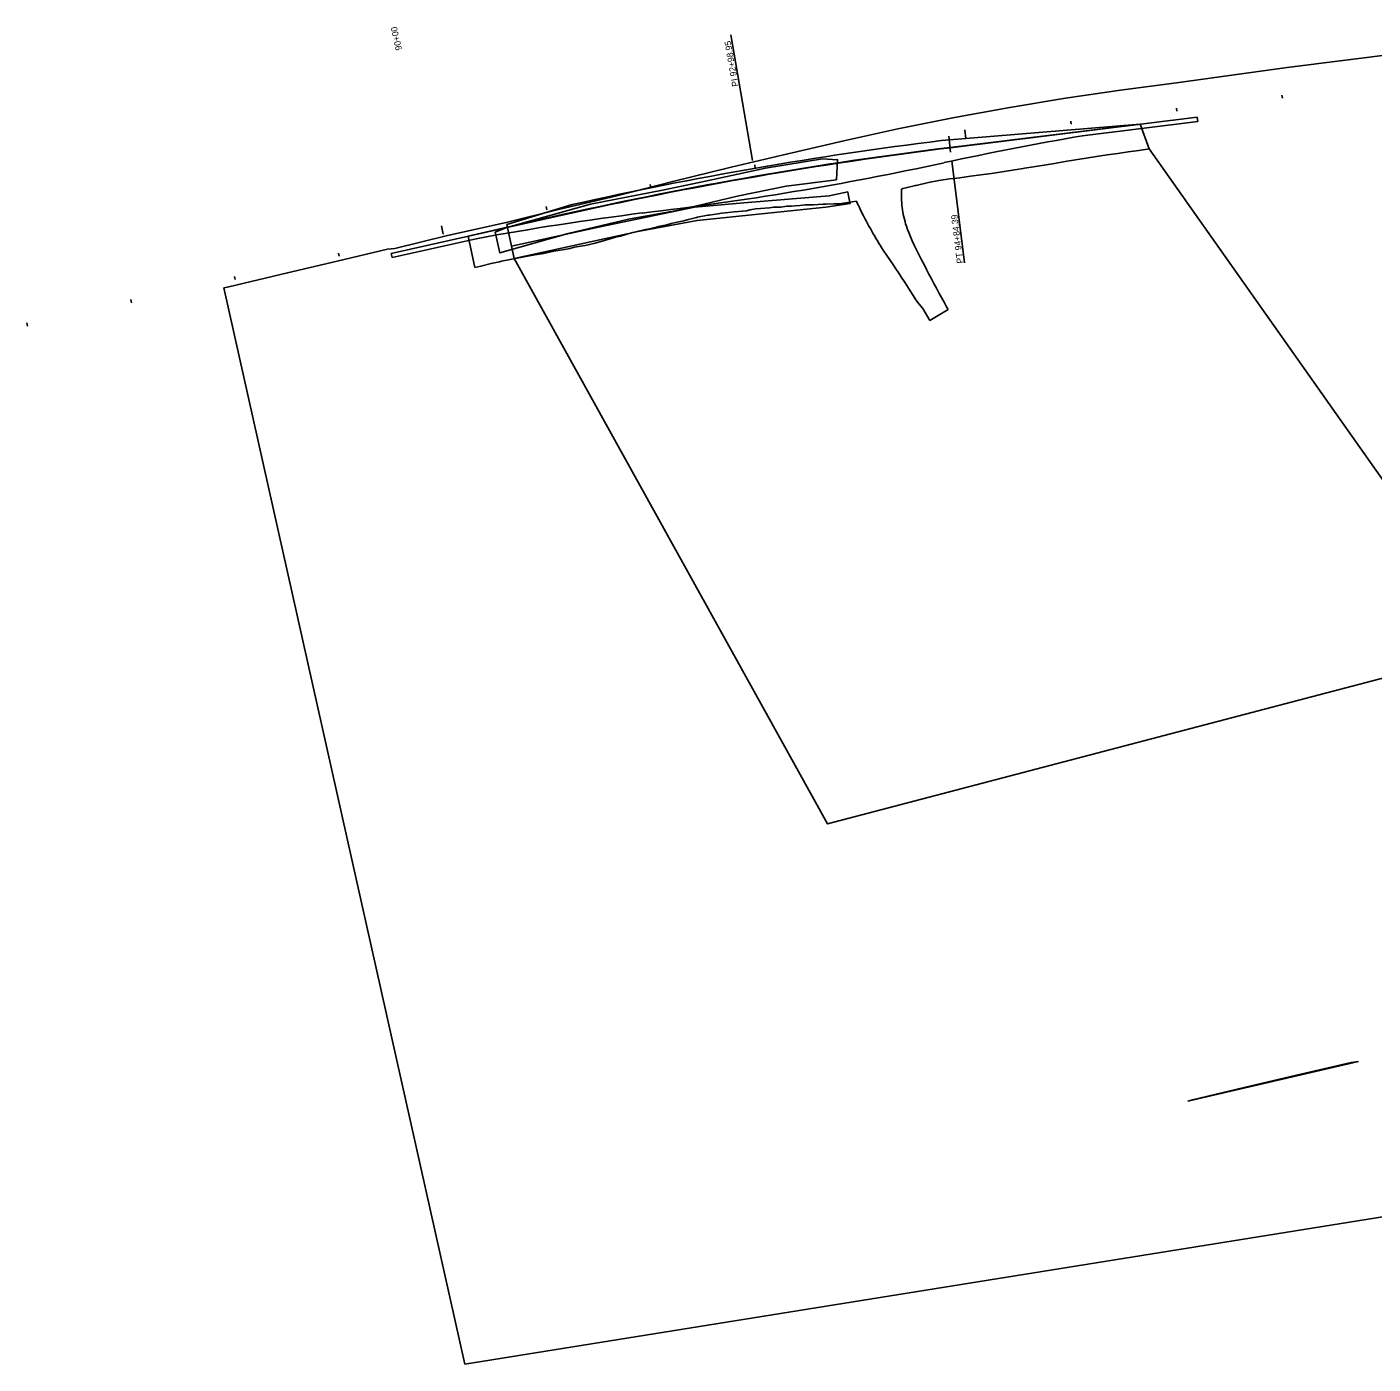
# Model space of a CAD drawing. Extents: x 1568908 to 1572777, y 730965 to 733090.
# Drawn here: x 1568908 to 1570174, y 730965 to 732222 of the extents above; entities that cross this region are included whole.
import ezdxf

# ---------------------------------------------------------------- set-up
doc = ezdxf.new("R2010")
doc.units = 0
doc.layers.add('R_Horz Alg Annot', color=7, linetype='Continuous')
doc.layers.add('R_No Plot', color=7, linetype='Continuous')

msp = doc.modelspace()

# ---------------------------------------------------------------- linework, layer by layer
at = {"layer": 'R_Horz Alg Annot'}
for points in [[(1569590.4, 732096.2), (1569569.9, 732214.4)], [(1570088.3, 732154.8), (1570087.9, 732157.7)], [(1569989, 732142.5), (1569988.7, 732145.5)], [(1569789.7, 732124.9), (1569790.7, 732117)], [(1569889.8, 732130.2), (1569889.4, 732133.2)], [(1569774.7, 732119), (1569776.5, 732104.1)], [(1569592.8, 732089), (1569592.3, 732092)], [(1569777.6, 732095.7), (1569789.4, 731999.9)], [(1569494.6, 732070.7), (1569494, 732073.6)], [(1569396.9, 732049.8), (1569396.2, 732052.8)], [(1569297.8, 732034.8), (1569299.5, 732027)], [(1569201.7, 732006.1), (1569201, 732009.1)], [(1569104.1, 731984.3), (1569103.5, 731987.2)], [(1569006.5, 731962.4), (1569005.9, 731965.4)], [(1568908.9, 731940.6), (1568908.3, 731943.5)]]:
    msp.add_lwpolyline(points, dxfattribs=at)
at = {"layer": 'R_No Plot'}
for p, q in [((1570008.2, 732136.8), (1569776, 732108.1)), ((1570008.7, 732132.8), (1570008.2, 732136.8)), ((1569954.7, 732130.2), (1569767.8, 732114.9)), ((1569954.7, 732130.2), (1569776, 732108.5)), ((1569900.4, 732119.4), (1570008.7, 732132.8)), ((1569963.2, 732107), (1569954.7, 732130.2)), ((1569420.8, 732054.8), (1569359.2, 732036.1)), ((1569411.5, 732044.9), (1569250.7, 732008.9)), ((1569411.5, 732045.3), (1569323.1, 732025.1)), ((1569486.7, 732046.8), (1569486.7, 732046.8)), ((1569251.6, 732005), (1569330.4, 732022.6)), ((1569323.1, 732025.1), (1569329.4, 731995.6)), ((1569247.2, 732012.7), (1569247.1, 732012.7)), ((1569247.2, 732012.7), (1569247.1, 732012.7)), ((1569247.2, 732012.7), (1569247.1, 732012.7)), ((1569247.2, 732012.7), (1569247.1, 732012.7)), ((1569254.2, 732013.6), (1569247.2, 732012.7)), ((1569254.2, 732013.6), (1569247.2, 732012.7)), ((1569254.2, 732013.6), (1569247.2, 732012.7)), ((1569254.2, 732013.6), (1569247.2, 732012.7)), ((1569250.7, 732008.9), (1569251.6, 732005)), ((1569093.5, 731976.4), (1569320, 730964.9)), ((1569093.5, 731976.4), (1569320, 730964.9)), ((1569093.5, 731976.4), (1569320, 730964.9)), ((1569093.5, 731976.4), (1569320, 730964.9)), ((1569774.2, 731956), (1569772.7, 731958.6)), ((1569750.3, 731957.2), (1569757, 731945.8)), ((1569757, 731945.8), (1569774.2, 731956)), ((1569320, 730964.9), (1572777.4, 731520)), ((1569320, 730964.9), (1572777.4, 731520)), ((1569320, 730964.9), (1572777.4, 731520)), ((1569320, 730964.9), (1572777.4, 731520)), ((1569999.3, 731212.1), (1570159.9, 731249.3)), ((1570159.9, 731249.3), (1570152.9, 731248.4)), ((1570152.9, 731248.4), (1570152.9, 731248.4))]:
    msp.add_line(p, q, dxfattribs=at)
for points in [[(1570197.5, 732196.8), (1570145.1, 732190.3), (1570092.9, 732183.6), (1570040.7, 732176.5), (1569988.9, 732169.3), (1569936.2, 732162.2), (1569884.5, 732154.7), (1569832.2, 732146), (1569780.2, 732136.6), (1569726.9, 732125.8), (1569676, 732114.6), (1569623.4, 732102.5), (1569570.3, 732089.8), (1569515.3, 732076.5), (1569462.6, 732063), (1569409.2, 732050.3), (1569358.8, 732037.8), (1569303.6, 732025.6), (1569254.2, 732013.6)], [(1570197.5, 732196.8), (1570145.1, 732190.3), (1570092.9, 732183.6), (1570040.7, 732176.5), (1569988.9, 732169.3), (1569936.2, 732162.2), (1569884.5, 732154.7), (1569832.2, 732146), (1569780.2, 732136.6), (1569726.9, 732125.8), (1569676, 732114.6), (1569623.4, 732102.5), (1569570.3, 732089.8), (1569515.3, 732076.5), (1569462.6, 732063), (1569409.2, 732050.3), (1569358.8, 732037.8), (1569303.6, 732025.6), (1569254.2, 732013.6)], [(1570197.5, 732196.8), (1570145.1, 732190.3), (1570092.9, 732183.6), (1570040.7, 732176.5), (1569988.9, 732169.3), (1569936.2, 732162.2), (1569884.5, 732154.7), (1569832.2, 732146), (1569780.2, 732136.6), (1569726.9, 732125.8), (1569676, 732114.6), (1569623.4, 732102.5), (1569570.3, 732089.8), (1569515.3, 732076.5), (1569462.6, 732063), (1569409.2, 732050.3), (1569358.8, 732037.8), (1569303.6, 732025.6), (1569254.2, 732013.6)], [(1570197.5, 732196.8), (1570145.1, 732190.3), (1570092.9, 732183.6), (1570040.7, 732176.5), (1569988.9, 732169.3), (1569936.2, 732162.2), (1569884.5, 732154.7), (1569832.2, 732146), (1569780.2, 732136.6), (1569726.9, 732125.8), (1569676, 732114.6), (1569623.4, 732102.5), (1569570.3, 732089.8), (1569515.3, 732076.5), (1569462.6, 732063), (1569409.2, 732050.3), (1569358.8, 732037.8), (1569303.6, 732025.6), (1569254.2, 732013.6)], [(1569359.2, 732036.1), (1569366.1, 732004.1), (1569660.8, 731472.6), (1570293.5, 731638.6), (1569963.2, 732107), (1569954.7, 732130.2)], [(1569755.6, 732075.6), (1569765.5, 732077.3), (1569767.5, 732077.6), (1569775.3, 732078.9), (1569779.6, 732079.3), (1569785.2, 732079.9), (1569795.1, 732081.3), (1569805, 732082.6), (1569814.9, 732083.9), (1569824.8, 732085.5), (1569834.7, 732087), (1569844.5, 732088.6), (1569846, 732088.9), (1569854.4, 732090.3), (1569864.3, 732091.9), (1569874.2, 732093.5), (1569884, 732095.2), (1569893.9, 732096.8), (1569903.8, 732098.4), (1569913.7, 732099.9), (1569923.6, 732101.4), (1569933.5, 732102.9), (1569943.4, 732104.3), (1569953.3, 732105.7), (1569963.2, 732107)], [(1569730.2, 732069.3), (1569731.5, 732069.7), (1569734.5, 732070.4), (1569743.4, 732072.7), (1569744.1, 732072.8), (1569755.6, 732075.6)], [(1569772.7, 731958.6), (1569770.3, 731962.9), (1569767.9, 731967.3), (1569765.4, 731971.7), (1569763.1, 731976.1), (1569760.7, 731980.5), (1569758.4, 731984.9), (1569756, 731989.4), (1569753.7, 731993.8), (1569751.5, 731998.3), (1569749.2, 732002.7), (1569746.9, 732007.2), (1569744.7, 732011.7), (1569742.4, 732016.1), (1569740.2, 732020.7), (1569738.4, 732025.4), (1569736.5, 732030), (1569736.4, 732030.3), (1569735.6, 732032.4), (1569734.9, 732034.4), (1569734.9, 732034.5), (1569734.2, 732036.7), (1569733.6, 732038.7), (1569733.6, 732038.8), (1569733, 732041), (1569732.5, 732043.1), (1569732.5, 732043.2), (1569732, 732045.4), (1569731.6, 732047.6), (1569731.6, 732047.6), (1569731.3, 732049.8), (1569731, 732052), (1569731, 732052), (1569730.7, 732054.2), (1569730.5, 732056.4), (1569730.5, 732056.5), (1569730.4, 732058.6), (1569730.3, 732060.8), (1569730.3, 732061), (1569730.2, 732063), (1569730.3, 732065.2), (1569730.3, 732065.4), (1569730.2, 732067.4), (1569730.2, 732069.3)], [(1569329.4, 731995.6), (1569335, 731996.8), (1569344.6, 731999.3), (1569352.6, 732001), (1569354.4, 732001.4), (1569364.2, 732003.5), (1569374, 732005.3), (1569383.9, 732007.1), (1569393.7, 732008.9), (1569403.6, 732010.8), (1569413.4, 732012.5), (1569418.5, 732013.6), (1569423.1, 732014.7), (1569430.5, 732016), (1569432.9, 732016.4), (1569442.5, 732018.4), (1569442.5, 732018.5), (1569452.1, 732021.2), (1569454.3, 732021.9), (1569461.6, 732024.1), (1569466.1, 732025.2), (1569471.1, 732026.7), (1569477.9, 732028.5), (1569480.7, 732029.1), (1569489.8, 732031.2), (1569490.4, 732031.3), (1569490.6, 732031.3), (1569500, 732033.6), (1569501.8, 732034), (1569509.6, 732035.8), (1569513.7, 732036.8), (1569519.3, 732038.1), (1569525.6, 732039.5), (1569528.9, 732040.4), (1569537.5, 732042.5), (1569538.5, 732042.8), (1569548.3, 732044.7), (1569549.5, 732044.9), (1569557.6, 732046.1), (1569561.5, 732046.6), (1569567.6, 732047.2), (1569573.1, 732048), (1569577.2, 732048.2), (1569584.6, 732048.8), (1569588, 732049.8), (1569593.1, 732050.6), (1569597.8, 732050.9), (1569606.2, 732051.6), (1569610, 732052.2), (1569616.8, 732052.4), (1569622.4, 732053.1), (1569626.9, 732053.4), (1569630.4, 732053.7), (1569634.8, 732053.8), (1569639.8, 732054.6), (1569646.9, 732054.6), (1569647.2, 732054.6), (1569656.8, 732055), (1569659.5, 732055.1), (1569666.8, 732055.3), (1569671.8, 732055.4), (1569688.1, 732058.1)], [(1569688.1, 732058.1), (1569689.4, 732054.7), (1569689.5, 732054.5), (1569690.7, 732051.9), (1569691.9, 732049.5), (1569691.9, 732049.4), (1569693.2, 732046.8), (1569694.4, 732044.4), (1569694.5, 732044.3), (1569695.8, 732041.8), (1569697, 732039.4), (1569697.1, 732039.4), (1569698.4, 732036.9), (1569699.7, 732034.5), (1569699.7, 732034.5), (1569701.1, 732032.1), (1569702.4, 732029.7), (1569702.5, 732029.6), (1569703.8, 732027.3), (1569705.2, 732024.9), (1569705.2, 732024.8), (1569706.6, 732022.6), (1569708, 732020.2), (1569708.1, 732020), (1569709.4, 732017.9), (1569710.8, 732015.6), (1569710.9, 732015.4), (1569713.6, 732011.1), (1569716.4, 732007), (1569719.2, 732002.8), (1569722.1, 731998.7), (1569724.9, 731994.5), (1569727.7, 731990.4), (1569730.4, 731986.2), (1569733.1, 731982), (1569735.9, 731977.8), (1569738.6, 731973.6), (1569741.2, 731969.3), (1569743.8, 731965.1), (1569746.8, 731961), (1569750.3, 731957.2)], [(1569247.1, 732012.7), (1569199.9, 732001.7), (1569153.3, 731990.5), (1569098, 731977.5), (1569093.5, 731976.4)], [(1569247.1, 732012.7), (1569199.9, 732001.7), (1569153.3, 731990.5), (1569098, 731977.5), (1569093.5, 731976.4)], [(1569247.1, 732012.7), (1569199.9, 732001.7), (1569153.3, 731990.5), (1569098, 731977.5), (1569093.5, 731976.4)], [(1569247.1, 732012.7), (1569199.9, 732001.7), (1569153.3, 731990.5), (1569098, 731977.5), (1569093.5, 731976.4)], [(1570152.9, 731248.4), (1570105.7, 731237.4), (1570059.1, 731226.3), (1570003.8, 731213.2), (1569999.3, 731212.1)]]:
    msp.add_lwpolyline(points, dxfattribs=at)
for points in [[(1569348.3, 732028.9), (1569352.8, 732009.3), (1569416.9, 732027.4), (1569473.7, 732041), (1569520.9, 732049.6), (1569576, 732062.7), (1569621.8, 732072.1), (1569669.2, 732078), (1569670.2, 732096.8), (1569656, 732097.6), (1569602.4, 732089), (1569546.1, 732076.9), (1569505.7, 732068.3), (1569438.1, 732055.2), (1569358.4, 732033)], [(1569680.9, 732061.4), (1569680.3, 732064.4), (1569679.8, 732066.7), (1569662.2, 732063), (1569582.2, 732056.3), (1569535.7, 732052.4), (1569445.6, 732033.6), (1569363.6, 732015.8), (1569366.1, 732004.1), (1569482.6, 732029.4), (1569538.2, 732039.8), (1569659.3, 732052.2), (1569682.1, 732055.8)]]:
    msp.add_lwpolyline(points, close=True, dxfattribs=at)
for centre, radius, start, end in [((1570212.7, 728516.8), 3625.5, 97.05, 102.6177), ((1570380, 729307.2), 2852.8, 99.6779, 102.3359), ((1570243.5, 728328.6), 3808.7, 97.05, 102.6177), ((1570243.5, 728328.2), 3808.7, 97.05, 102.6177), ((1569155.9, 734904.5), 2876.8, 276.6023, 282.3359), ((1569844.5, 729218), 2851.4, 97.209, 100.3874)]:
    msp.add_arc(centre, radius, start, end, dxfattribs=at)

# ---------------------------------------------------------------- texts
at = {"layer": 'R_Horz Alg Annot'}
for s, rotation, p in [('90+00', 102.6177, (1569260.9, 732200.4)), ('PI 92+98.95', 99.8339, (1569577.2, 732166.2)), ('PT 94+84.39', 97.05, (1569788.4, 731999.8))]:
    msp.add_text(s, height=6, rotation=rotation, dxfattribs=at).set_placement(p)

doc.saveas('drawing.dxf')
